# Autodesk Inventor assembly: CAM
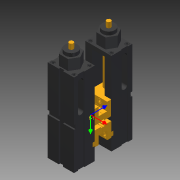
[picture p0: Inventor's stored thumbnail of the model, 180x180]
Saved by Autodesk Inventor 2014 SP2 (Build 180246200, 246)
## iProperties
Created: 2005-05
Part Number: CAM
Document SubType Name: Assembly
Designer: Administrator
Mass: 8692.88 g
Surface Area: 10150.6 cm^2
Volume: 8677.37 cm^3
Density: 1.00179 g/cm^3
Author: Administrator
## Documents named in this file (3)
- Z:\VDW-Nachwuchsstiftung Intern\Mitarbeiter Ablage\Steffen Krauth\IVCAM\KnowledgeBase Daten\NADELHALTER_UNTEN\NADELHALTER_UNTEN.IAM
- Z:\VDW-Nachwuchsstiftung Intern\Mitarbeiter Ablage\Steffen Krauth\IVCAM\KnowledgeBase Daten\NADELHALTER_UNTEN\DesignModel.iam
- Z:\VDW-Nachwuchsstiftung Intern\Mitarbeiter Ablage\Steffen Krauth\IVCAM\KnowledgeBase Daten\NADELHALTER_UNTEN\CAM.IPT
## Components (2 placed, 2 different names)
1. DesignModel:1 [sub-assembly]
2. CAM:1
